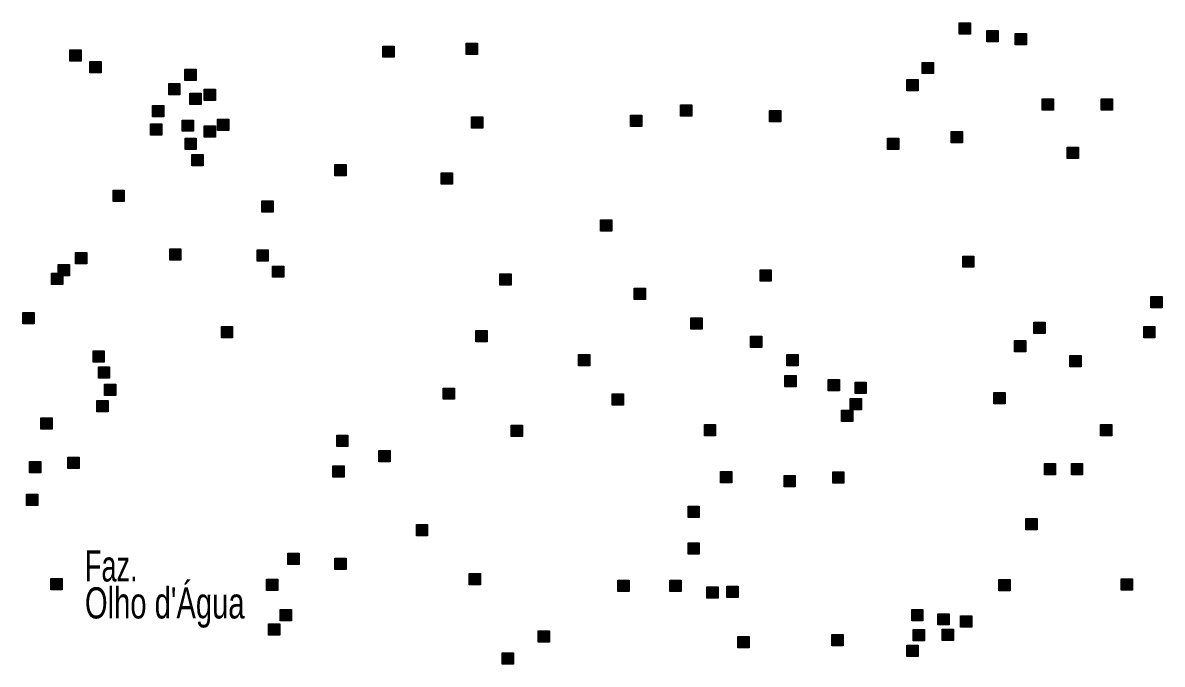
# Model space of a CAD drawing. Extents: x 445.4 to 500, y 8728.7 to 8784.
# Drawn here: x 494.04 to 499.9, y 8774.1 to 8777.39 of the extents above; entities that cross this region are included whole.
import ezdxf

# ---------------------------------------------------------------- set-up
doc = ezdxf.new("R2010")
doc.units = 0
doc.header["$LTSCALE"] = 0.064
doc.layers.add('2', color=7, linetype='Continuous', lineweight=25)
doc.layers.add('61', color=7, linetype='Continuous')

msp = doc.modelspace()

# ---------------------------------------------------------------- hatches: boundary and pattern name
at = {"layer": '2'}
for points in [[(498.8532, 8777.392), (498.9112, 8777.392), (498.9112, 8777.334), (498.8532, 8777.334)], [(498.9955, 8777.3518), (499.0535, 8777.3518), (499.0535, 8777.2938), (498.9955, 8777.2938)], [(499.1414, 8777.3372), (499.1994, 8777.3372), (499.1994, 8777.2792), (499.1414, 8777.2792)], [(495.8935, 8777.2728), (495.9515, 8777.2728), (495.9515, 8777.2148), (495.8935, 8777.2148)], [(496.3223, 8777.2875), (496.3803, 8777.2875), (496.3803, 8777.2295), (496.3223, 8777.2295)], [(494.2865, 8777.253), (494.3445, 8777.253), (494.3445, 8777.195), (494.2865, 8777.195)], [(494.39, 8777.1938), (494.448, 8777.1938), (494.448, 8777.1358), (494.39, 8777.1358)], [(494.8773, 8777.1544), (494.9353, 8777.1544), (494.9353, 8777.0964), (494.8773, 8777.0964)], [(498.6637, 8777.1889), (498.7217, 8777.1889), (498.7217, 8777.1309), (498.6637, 8777.1309)], [(498.5848, 8777.1001), (498.6428, 8777.1001), (498.6428, 8777.0421), (498.5848, 8777.0421)], [(494.7942, 8777.0804), (494.8522, 8777.0804), (494.8522, 8777.0224), (494.7942, 8777.0224)], [(494.9766, 8777.0508), (495.0346, 8777.0508), (495.0346, 8776.9928), (494.9766, 8776.9928)], [(494.9027, 8777.0311), (494.9607, 8777.0311), (494.9607, 8776.9731), (494.9027, 8776.9731)], [(499.28, 8777.0014), (499.338, 8777.0014), (499.338, 8776.9434), (499.28, 8776.9434)], [(499.5828, 8777.0014), (499.6408, 8777.0014), (499.6408, 8776.9434), (499.5828, 8776.9434)], [(494.7104, 8776.967), (494.7684, 8776.967), (494.7684, 8776.909), (494.7104, 8776.909)], [(497.1652, 8776.9177), (497.2232, 8776.9177), (497.2232, 8776.8597), (497.1652, 8776.8597)], [(497.4222, 8776.9714), (497.4802, 8776.9714), (497.4802, 8776.9134), (497.4222, 8776.9134)], [(497.8799, 8776.9423), (497.9379, 8776.9423), (497.9379, 8776.8843), (497.8799, 8776.8843)], [(494.7006, 8776.8733), (494.7586, 8776.8733), (494.7586, 8776.8153), (494.7006, 8776.8153)], [(494.8632, 8776.893), (494.9212, 8776.893), (494.9212, 8776.835), (494.8632, 8776.835)], [(494.9766, 8776.8634), (495.0346, 8776.8634), (495.0346, 8776.8054), (494.9766, 8776.8054)], [(495.0456, 8776.8979), (495.1036, 8776.8979), (495.1036, 8776.8399), (495.0456, 8776.8399)], [(496.3493, 8776.9094), (496.4073, 8776.9094), (496.4073, 8776.8514), (496.3493, 8776.8514)], [(498.8131, 8776.8335), (498.8711, 8776.8335), (498.8711, 8776.7755), (498.8131, 8776.7755)], [(494.878, 8776.7993), (494.936, 8776.7993), (494.936, 8776.7413), (494.878, 8776.7413)], [(498.4862, 8776.7993), (498.5442, 8776.7993), (498.5442, 8776.7413), (498.4862, 8776.7413)], [(499.4077, 8776.7532), (499.4657, 8776.7532), (499.4657, 8776.6952), (499.4077, 8776.6952)], [(494.9125, 8776.7155), (494.9705, 8776.7155), (494.9705, 8776.6575), (494.9125, 8776.6575)], [(495.6477, 8776.6646), (495.7057, 8776.6646), (495.7057, 8776.6066), (495.6477, 8776.6066)], [(496.1941, 8776.6218), (496.2521, 8776.6218), (496.2521, 8776.5638), (496.1941, 8776.5638)], [(494.5083, 8776.533), (494.5663, 8776.533), (494.5663, 8776.475), (494.5083, 8776.475)], [(495.2724, 8776.4787), (495.3304, 8776.4787), (495.3304, 8776.4207), (495.2724, 8776.4207)], [(497.0124, 8776.3801), (497.0704, 8776.3801), (497.0704, 8776.3221), (497.0124, 8776.3221)], [(494.7992, 8776.2322), (494.8572, 8776.2322), (494.8572, 8776.1742), (494.7992, 8776.1742)], [(495.2477, 8776.2272), (495.3057, 8776.2272), (495.3057, 8776.1692), (495.2477, 8776.1692)], [(494.3161, 8776.2124), (494.3741, 8776.2124), (494.3741, 8776.1544), (494.3161, 8776.1544)], [(498.8714, 8776.1948), (498.9294, 8776.1948), (498.9294, 8776.1368), (498.8714, 8776.1368)], [(494.1928, 8776.1068), (494.2508, 8776.1068), (494.2508, 8776.0488), (494.1928, 8776.0488)], [(494.2273, 8776.1512), (494.2853, 8776.1512), (494.2853, 8776.0932), (494.2273, 8776.0932)], [(495.3266, 8776.1434), (495.3846, 8776.1434), (495.3846, 8776.0854), (495.3266, 8776.0854)], [(496.4948, 8776.1039), (496.5528, 8776.1039), (496.5528, 8776.0459), (496.4948, 8776.0459)], [(497.8307, 8776.1237), (497.8887, 8776.1237), (497.8887, 8776.0657), (497.8307, 8776.0657)], [(497.1849, 8776.03), (497.2429, 8776.03), (497.2429, 8775.972), (497.1849, 8775.972)], [(499.8381, 8775.9867), (499.8961, 8775.9867), (499.8961, 8775.9287), (499.8381, 8775.9287)], [(494.0449, 8775.9046), (494.1029, 8775.9046), (494.1029, 8775.8466), (494.0449, 8775.8466)], [(497.4757, 8775.8771), (497.5337, 8775.8771), (497.5337, 8775.8191), (497.4757, 8775.8191)], [(495.0646, 8775.8327), (495.1226, 8775.8327), (495.1226, 8775.7747), (495.0646, 8775.7747)], [(496.3716, 8775.813), (496.4296, 8775.813), (496.4296, 8775.755), (496.3716, 8775.755)], [(499.2362, 8775.8553), (499.2942, 8775.8553), (499.2942, 8775.7973), (499.2362, 8775.7973)], [(499.8009, 8775.833), (499.8589, 8775.833), (499.8589, 8775.775), (499.8009, 8775.775)], [(497.7814, 8775.7834), (497.8394, 8775.7834), (497.8394, 8775.7254), (497.7814, 8775.7254)], [(499.1377, 8775.7604), (499.1957, 8775.7604), (499.1957, 8775.7024), (499.1377, 8775.7024)], [(494.4055, 8775.7079), (494.4635, 8775.7079), (494.4635, 8775.6499), (494.4055, 8775.6499)], [(496.899, 8775.6897), (496.957, 8775.6897), (496.957, 8775.6317), (496.899, 8775.6317)], [(497.9687, 8775.6897), (498.0267, 8775.6897), (498.0267, 8775.6317), (497.9687, 8775.6317)], [(499.4223, 8775.6838), (499.4803, 8775.6838), (499.4803, 8775.6258), (499.4223, 8775.6258)], [(494.4329, 8775.6263), (494.4909, 8775.6263), (494.4909, 8775.5683), (494.4329, 8775.5683)], [(497.9588, 8775.5812), (498.0168, 8775.5812), (498.0168, 8775.5232), (497.9588, 8775.5232)], [(494.464, 8775.5368), (494.522, 8775.5368), (494.522, 8775.4788), (494.464, 8775.4788)], [(496.204, 8775.5171), (496.262, 8775.5171), (496.262, 8775.4591), (496.204, 8775.4591)], [(498.1806, 8775.5615), (498.2386, 8775.5615), (498.2386, 8775.5035), (498.1806, 8775.5035)], [(498.3186, 8775.5467), (498.3766, 8775.5467), (498.3766, 8775.4887), (498.3186, 8775.4887)], [(497.0715, 8775.4875), (497.1295, 8775.4875), (497.1295, 8775.4295), (497.0715, 8775.4295)], [(498.294, 8775.4628), (498.352, 8775.4628), (498.352, 8775.4048), (498.294, 8775.4048)], [(499.0319, 8775.494), (499.0899, 8775.494), (499.0899, 8775.436), (499.0319, 8775.436)], [(494.4245, 8775.453), (494.4825, 8775.453), (494.4825, 8775.395), (494.4245, 8775.395)], [(498.2496, 8775.4036), (498.3076, 8775.4036), (498.3076, 8775.3456), (498.2496, 8775.3456)], [(494.1371, 8775.3639), (494.1951, 8775.3639), (494.1951, 8775.3059), (494.1371, 8775.3059)], [(496.5533, 8775.3259), (496.6113, 8775.3259), (496.6113, 8775.2679), (496.5533, 8775.2679)], [(497.5448, 8775.3297), (497.6028, 8775.3297), (497.6028, 8775.2717), (497.5448, 8775.2717)], [(499.5787, 8775.33), (499.6367, 8775.33), (499.6367, 8775.272), (499.5787, 8775.272)], [(495.6569, 8775.2754), (495.7149, 8775.2754), (495.7149, 8775.2174), (495.6569, 8775.2174)], [(494.2767, 8775.162), (494.3347, 8775.162), (494.3347, 8775.104), (494.2767, 8775.104)], [(495.8737, 8775.1965), (495.9317, 8775.1965), (495.9317, 8775.1385), (495.8737, 8775.1385)], [(494.0794, 8775.1402), (494.1374, 8775.1402), (494.1374, 8775.0822), (494.0794, 8775.0822)], [(495.6371, 8775.1176), (495.6951, 8775.1176), (495.6951, 8775.0596), (495.6371, 8775.0596)], [(499.2909, 8775.129), (499.3489, 8775.129), (499.3489, 8775.071), (499.2909, 8775.071)], [(499.4296, 8775.129), (499.4876, 8775.129), (499.4876, 8775.071), (499.4296, 8775.071)], [(497.6286, 8775.088), (497.6866, 8775.088), (497.6866, 8775.03), (497.6286, 8775.03)], [(497.9539, 8775.0683), (498.0119, 8775.0683), (498.0119, 8775.0103), (497.9539, 8775.0103)], [(498.2039, 8775.0873), (498.2619, 8775.0873), (498.2619, 8775.0293), (498.2039, 8775.0293)], [(494.0647, 8774.9725), (494.1227, 8774.9725), (494.1227, 8774.9145), (494.0647, 8774.9145)], [(497.461, 8774.9105), (497.519, 8774.9105), (497.519, 8774.8525), (497.461, 8774.8525)], [(496.066, 8774.8168), (496.124, 8774.8168), (496.124, 8774.7588), (496.066, 8774.7588)], [(499.1961, 8774.8479), (499.2541, 8774.8479), (499.2541, 8774.7899), (499.1961, 8774.7899)], [(497.461, 8774.7231), (497.519, 8774.7231), (497.519, 8774.6651), (497.461, 8774.6651)], [(495.4055, 8774.6688), (495.4635, 8774.6688), (495.4635, 8774.6108), (495.4055, 8774.6108)], [(495.647, 8774.6442), (495.705, 8774.6442), (495.705, 8774.5862), (495.647, 8774.5862)], [(494.1894, 8774.5392), (494.2474, 8774.5392), (494.2474, 8774.4812), (494.1894, 8774.4812)], [(495.297, 8774.5357), (495.355, 8774.5357), (495.355, 8774.4777), (495.297, 8774.4777)], [(496.3371, 8774.5652), (496.3951, 8774.5652), (496.3951, 8774.5072), (496.3371, 8774.5072)], [(497.1011, 8774.5307), (497.1591, 8774.5307), (497.1591, 8774.4727), (497.1011, 8774.4727)], [(497.3673, 8774.5307), (497.4253, 8774.5307), (497.4253, 8774.4727), (497.3673, 8774.4727)], [(499.0575, 8774.534), (499.1155, 8774.534), (499.1155, 8774.476), (499.0575, 8774.476)], [(499.6849, 8774.5383), (499.7429, 8774.5383), (499.7429, 8774.4803), (499.6849, 8774.4803)], [(497.5579, 8774.4966), (497.6159, 8774.4966), (497.6159, 8774.4386), (497.5579, 8774.4386)], [(497.6605, 8774.5004), (497.7185, 8774.5004), (497.7185, 8774.4424), (497.6605, 8774.4424)], [(495.366, 8774.3798), (495.424, 8774.3798), (495.424, 8774.3218), (495.366, 8774.3218)], [(498.6095, 8774.3798), (498.6675, 8774.3798), (498.6675, 8774.3218), (498.6095, 8774.3218)], [(498.7438, 8774.3588), (498.8018, 8774.3588), (498.8018, 8774.3008), (498.7438, 8774.3008)], [(498.8605, 8774.3478), (498.9185, 8774.3478), (498.9185, 8774.2898), (498.8605, 8774.2898)], [(495.3069, 8774.3059), (495.3649, 8774.3059), (495.3649, 8774.2479), (495.3069, 8774.2479)], [(496.692, 8774.2713), (496.75, 8774.2713), (496.75, 8774.2133), (496.692, 8774.2133)], [(497.7173, 8774.2418), (497.7753, 8774.2418), (497.7753, 8774.1838), (497.7173, 8774.1838)], [(498.2003, 8774.2516), (498.2583, 8774.2516), (498.2583, 8774.1936), (498.2003, 8774.1936)], [(498.6167, 8774.2778), (498.6747, 8774.2778), (498.6747, 8774.2198), (498.6167, 8774.2198)], [(498.7656, 8774.2785), (498.8236, 8774.2785), (498.8236, 8774.2205), (498.7656, 8774.2205)], [(498.5848, 8774.1974), (498.6428, 8774.1974), (498.6428, 8774.1394), (498.5848, 8774.1394)], [(496.5065, 8774.1574), (496.5645, 8774.1574), (496.5645, 8774.0994), (496.5065, 8774.0994)]]:
    msp.add_hatch(color=256, dxfattribs=at).paths.add_polyline_path(points)

# ---------------------------------------------------------------- linework, layer by layer
for points in [[(498.8532, 8777.392), (498.9112, 8777.392), (498.9112, 8777.334), (498.8532, 8777.334)], [(498.9955, 8777.3518), (499.0535, 8777.3518), (499.0535, 8777.2938), (498.9955, 8777.2938)], [(499.1414, 8777.3372), (499.1994, 8777.3372), (499.1994, 8777.2792), (499.1414, 8777.2792)], [(495.8935, 8777.2728), (495.9515, 8777.2728), (495.9515, 8777.2148), (495.8935, 8777.2148)], [(496.3223, 8777.2875), (496.3803, 8777.2875), (496.3803, 8777.2295), (496.3223, 8777.2295)], [(494.2865, 8777.253), (494.3445, 8777.253), (494.3445, 8777.195), (494.2865, 8777.195)], [(494.39, 8777.1938), (494.448, 8777.1938), (494.448, 8777.1358), (494.39, 8777.1358)], [(494.8773, 8777.1544), (494.9353, 8777.1544), (494.9353, 8777.0964), (494.8773, 8777.0964)], [(498.6637, 8777.1889), (498.7217, 8777.1889), (498.7217, 8777.1309), (498.6637, 8777.1309)], [(498.5848, 8777.1001), (498.6428, 8777.1001), (498.6428, 8777.0421), (498.5848, 8777.0421)], [(494.7942, 8777.0804), (494.8522, 8777.0804), (494.8522, 8777.0224), (494.7942, 8777.0224)], [(494.9766, 8777.0508), (495.0346, 8777.0508), (495.0346, 8776.9928), (494.9766, 8776.9928)], [(494.9027, 8777.0311), (494.9607, 8777.0311), (494.9607, 8776.9731), (494.9027, 8776.9731)], [(499.28, 8777.0014), (499.338, 8777.0014), (499.338, 8776.9434), (499.28, 8776.9434)], [(499.5828, 8777.0014), (499.6408, 8777.0014), (499.6408, 8776.9434), (499.5828, 8776.9434)], [(494.7104, 8776.967), (494.7684, 8776.967), (494.7684, 8776.909), (494.7104, 8776.909)], [(497.1652, 8776.9177), (497.2232, 8776.9177), (497.2232, 8776.8597), (497.1652, 8776.8597)], [(497.4222, 8776.9714), (497.4802, 8776.9714), (497.4802, 8776.9134), (497.4222, 8776.9134)], [(497.8799, 8776.9423), (497.9379, 8776.9423), (497.9379, 8776.8843), (497.8799, 8776.8843)], [(494.7006, 8776.8733), (494.7586, 8776.8733), (494.7586, 8776.8153), (494.7006, 8776.8153)], [(494.8632, 8776.893), (494.9212, 8776.893), (494.9212, 8776.835), (494.8632, 8776.835)], [(494.9766, 8776.8634), (495.0346, 8776.8634), (495.0346, 8776.8054), (494.9766, 8776.8054)], [(495.0456, 8776.8979), (495.1036, 8776.8979), (495.1036, 8776.8399), (495.0456, 8776.8399)], [(496.3493, 8776.9094), (496.4073, 8776.9094), (496.4073, 8776.8514), (496.3493, 8776.8514)], [(498.8131, 8776.8335), (498.8711, 8776.8335), (498.8711, 8776.7755), (498.8131, 8776.7755)], [(494.878, 8776.7993), (494.936, 8776.7993), (494.936, 8776.7413), (494.878, 8776.7413)], [(498.4862, 8776.7993), (498.5442, 8776.7993), (498.5442, 8776.7413), (498.4862, 8776.7413)], [(499.4077, 8776.7532), (499.4657, 8776.7532), (499.4657, 8776.6952), (499.4077, 8776.6952)], [(494.9125, 8776.7155), (494.9705, 8776.7155), (494.9705, 8776.6575), (494.9125, 8776.6575)], [(495.6477, 8776.6646), (495.7057, 8776.6646), (495.7057, 8776.6066), (495.6477, 8776.6066)], [(496.1941, 8776.6218), (496.2521, 8776.6218), (496.2521, 8776.5638), (496.1941, 8776.5638)], [(494.5083, 8776.533), (494.5663, 8776.533), (494.5663, 8776.475), (494.5083, 8776.475)], [(495.2724, 8776.4787), (495.3304, 8776.4787), (495.3304, 8776.4207), (495.2724, 8776.4207)], [(497.0124, 8776.3801), (497.0704, 8776.3801), (497.0704, 8776.3221), (497.0124, 8776.3221)], [(494.7992, 8776.2322), (494.8572, 8776.2322), (494.8572, 8776.1742), (494.7992, 8776.1742)], [(495.2477, 8776.2272), (495.3057, 8776.2272), (495.3057, 8776.1692), (495.2477, 8776.1692)], [(494.3161, 8776.2124), (494.3741, 8776.2124), (494.3741, 8776.1544), (494.3161, 8776.1544)], [(498.8714, 8776.1948), (498.9294, 8776.1948), (498.9294, 8776.1368), (498.8714, 8776.1368)], [(494.1928, 8776.1068), (494.2508, 8776.1068), (494.2508, 8776.0488), (494.1928, 8776.0488)], [(494.2273, 8776.1512), (494.2853, 8776.1512), (494.2853, 8776.0932), (494.2273, 8776.0932)], [(495.3266, 8776.1434), (495.3846, 8776.1434), (495.3846, 8776.0854), (495.3266, 8776.0854)], [(496.4948, 8776.1039), (496.5528, 8776.1039), (496.5528, 8776.0459), (496.4948, 8776.0459)], [(497.8307, 8776.1237), (497.8887, 8776.1237), (497.8887, 8776.0657), (497.8307, 8776.0657)], [(497.1849, 8776.03), (497.2429, 8776.03), (497.2429, 8775.972), (497.1849, 8775.972)], [(499.8381, 8775.9867), (499.8961, 8775.9867), (499.8961, 8775.9287), (499.8381, 8775.9287)], [(494.0449, 8775.9046), (494.1029, 8775.9046), (494.1029, 8775.8466), (494.0449, 8775.8466)], [(497.4757, 8775.8771), (497.5337, 8775.8771), (497.5337, 8775.8191), (497.4757, 8775.8191)], [(495.0646, 8775.8327), (495.1226, 8775.8327), (495.1226, 8775.7747), (495.0646, 8775.7747)], [(496.3716, 8775.813), (496.4296, 8775.813), (496.4296, 8775.755), (496.3716, 8775.755)], [(499.2362, 8775.8553), (499.2942, 8775.8553), (499.2942, 8775.7973), (499.2362, 8775.7973)], [(499.8009, 8775.833), (499.8589, 8775.833), (499.8589, 8775.775), (499.8009, 8775.775)], [(497.7814, 8775.7834), (497.8394, 8775.7834), (497.8394, 8775.7254), (497.7814, 8775.7254)], [(499.1377, 8775.7604), (499.1957, 8775.7604), (499.1957, 8775.7024), (499.1377, 8775.7024)], [(494.4055, 8775.7079), (494.4635, 8775.7079), (494.4635, 8775.6499), (494.4055, 8775.6499)], [(496.899, 8775.6897), (496.957, 8775.6897), (496.957, 8775.6317), (496.899, 8775.6317)], [(497.9687, 8775.6897), (498.0267, 8775.6897), (498.0267, 8775.6317), (497.9687, 8775.6317)], [(499.4223, 8775.6838), (499.4803, 8775.6838), (499.4803, 8775.6258), (499.4223, 8775.6258)], [(494.4329, 8775.6263), (494.4909, 8775.6263), (494.4909, 8775.5683), (494.4329, 8775.5683)], [(497.9588, 8775.5812), (498.0168, 8775.5812), (498.0168, 8775.5232), (497.9588, 8775.5232)], [(494.464, 8775.5368), (494.522, 8775.5368), (494.522, 8775.4788), (494.464, 8775.4788)], [(496.204, 8775.5171), (496.262, 8775.5171), (496.262, 8775.4591), (496.204, 8775.4591)], [(498.1806, 8775.5615), (498.2386, 8775.5615), (498.2386, 8775.5035), (498.1806, 8775.5035)], [(498.3186, 8775.5467), (498.3766, 8775.5467), (498.3766, 8775.4887), (498.3186, 8775.4887)], [(497.0715, 8775.4875), (497.1295, 8775.4875), (497.1295, 8775.4295), (497.0715, 8775.4295)], [(498.294, 8775.4628), (498.352, 8775.4628), (498.352, 8775.4048), (498.294, 8775.4048)], [(499.0319, 8775.494), (499.0899, 8775.494), (499.0899, 8775.436), (499.0319, 8775.436)], [(494.4245, 8775.453), (494.4825, 8775.453), (494.4825, 8775.395), (494.4245, 8775.395)], [(498.2496, 8775.4036), (498.3076, 8775.4036), (498.3076, 8775.3456), (498.2496, 8775.3456)], [(494.1371, 8775.3639), (494.1951, 8775.3639), (494.1951, 8775.3059), (494.1371, 8775.3059)], [(496.5533, 8775.3259), (496.6113, 8775.3259), (496.6113, 8775.2679), (496.5533, 8775.2679)], [(497.5448, 8775.3297), (497.6028, 8775.3297), (497.6028, 8775.2717), (497.5448, 8775.2717)], [(499.5787, 8775.33), (499.6367, 8775.33), (499.6367, 8775.272), (499.5787, 8775.272)], [(495.6569, 8775.2754), (495.7149, 8775.2754), (495.7149, 8775.2174), (495.6569, 8775.2174)], [(494.2767, 8775.162), (494.3347, 8775.162), (494.3347, 8775.104), (494.2767, 8775.104)], [(495.8737, 8775.1965), (495.9317, 8775.1965), (495.9317, 8775.1385), (495.8737, 8775.1385)], [(494.0794, 8775.1402), (494.1374, 8775.1402), (494.1374, 8775.0822), (494.0794, 8775.0822)], [(495.6371, 8775.1176), (495.6951, 8775.1176), (495.6951, 8775.0596), (495.6371, 8775.0596)], [(499.2909, 8775.129), (499.3489, 8775.129), (499.3489, 8775.071), (499.2909, 8775.071)], [(499.4296, 8775.129), (499.4876, 8775.129), (499.4876, 8775.071), (499.4296, 8775.071)], [(497.6286, 8775.088), (497.6866, 8775.088), (497.6866, 8775.03), (497.6286, 8775.03)], [(497.9539, 8775.0683), (498.0119, 8775.0683), (498.0119, 8775.0103), (497.9539, 8775.0103)], [(498.2039, 8775.0873), (498.2619, 8775.0873), (498.2619, 8775.0293), (498.2039, 8775.0293)], [(494.0647, 8774.9725), (494.1227, 8774.9725), (494.1227, 8774.9145), (494.0647, 8774.9145)], [(497.461, 8774.9105), (497.519, 8774.9105), (497.519, 8774.8525), (497.461, 8774.8525)], [(496.066, 8774.8168), (496.124, 8774.8168), (496.124, 8774.7588), (496.066, 8774.7588)], [(499.1961, 8774.8479), (499.2541, 8774.8479), (499.2541, 8774.7899), (499.1961, 8774.7899)], [(497.461, 8774.7231), (497.519, 8774.7231), (497.519, 8774.6651), (497.461, 8774.6651)], [(495.4055, 8774.6688), (495.4635, 8774.6688), (495.4635, 8774.6108), (495.4055, 8774.6108)], [(495.647, 8774.6442), (495.705, 8774.6442), (495.705, 8774.5862), (495.647, 8774.5862)], [(494.1894, 8774.5392), (494.2474, 8774.5392), (494.2474, 8774.4812), (494.1894, 8774.4812)], [(495.297, 8774.5357), (495.355, 8774.5357), (495.355, 8774.4777), (495.297, 8774.4777)], [(496.3371, 8774.5652), (496.3951, 8774.5652), (496.3951, 8774.5072), (496.3371, 8774.5072)], [(497.1011, 8774.5307), (497.1591, 8774.5307), (497.1591, 8774.4727), (497.1011, 8774.4727)], [(497.3673, 8774.5307), (497.4253, 8774.5307), (497.4253, 8774.4727), (497.3673, 8774.4727)], [(499.0575, 8774.534), (499.1155, 8774.534), (499.1155, 8774.476), (499.0575, 8774.476)], [(499.6849, 8774.5383), (499.7429, 8774.5383), (499.7429, 8774.4803), (499.6849, 8774.4803)], [(497.5579, 8774.4966), (497.6159, 8774.4966), (497.6159, 8774.4386), (497.5579, 8774.4386)], [(497.6605, 8774.5004), (497.7185, 8774.5004), (497.7185, 8774.4424), (497.6605, 8774.4424)], [(495.366, 8774.3798), (495.424, 8774.3798), (495.424, 8774.3218), (495.366, 8774.3218)], [(498.6095, 8774.3798), (498.6675, 8774.3798), (498.6675, 8774.3218), (498.6095, 8774.3218)], [(498.7438, 8774.3588), (498.8018, 8774.3588), (498.8018, 8774.3008), (498.7438, 8774.3008)], [(498.8605, 8774.3478), (498.9185, 8774.3478), (498.9185, 8774.2898), (498.8605, 8774.2898)], [(495.3069, 8774.3059), (495.3649, 8774.3059), (495.3649, 8774.2479), (495.3069, 8774.2479)], [(496.692, 8774.2713), (496.75, 8774.2713), (496.75, 8774.2133), (496.692, 8774.2133)], [(497.7173, 8774.2418), (497.7753, 8774.2418), (497.7753, 8774.1838), (497.7173, 8774.1838)], [(498.2003, 8774.2516), (498.2583, 8774.2516), (498.2583, 8774.1936), (498.2003, 8774.1936)], [(498.6167, 8774.2778), (498.6747, 8774.2778), (498.6747, 8774.2198), (498.6167, 8774.2198)], [(498.7656, 8774.2785), (498.8236, 8774.2785), (498.8236, 8774.2205), (498.7656, 8774.2205)], [(498.5848, 8774.1974), (498.6428, 8774.1974), (498.6428, 8774.1394), (498.5848, 8774.1394)], [(496.5065, 8774.1574), (496.5645, 8774.1574), (496.5645, 8774.0994), (496.5065, 8774.0994)]]:
    msp.add_lwpolyline(points, close=True, dxfattribs=at)

# ---------------------------------------------------------------- texts
at = {"layer": '61'}
for s, width, p in [('Faz.', 0.65, (494.364, 8774.5242)), ("Olho d'Água", 0.7, (494.364, 8774.3342))]:
    msp.add_text(s, height=0.16, dxfattribs=dict(at, width=width)).set_placement(p)

doc.saveas('drawing.dxf')
